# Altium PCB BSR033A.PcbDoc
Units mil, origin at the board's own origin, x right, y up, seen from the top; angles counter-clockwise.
Board outline 1950 x 1400 mil, 2 copper layers (Top Layer, Bottom Layer), stack 61.2 mil thick; 52 components, 17 nets, 86 pads, 24 vias.
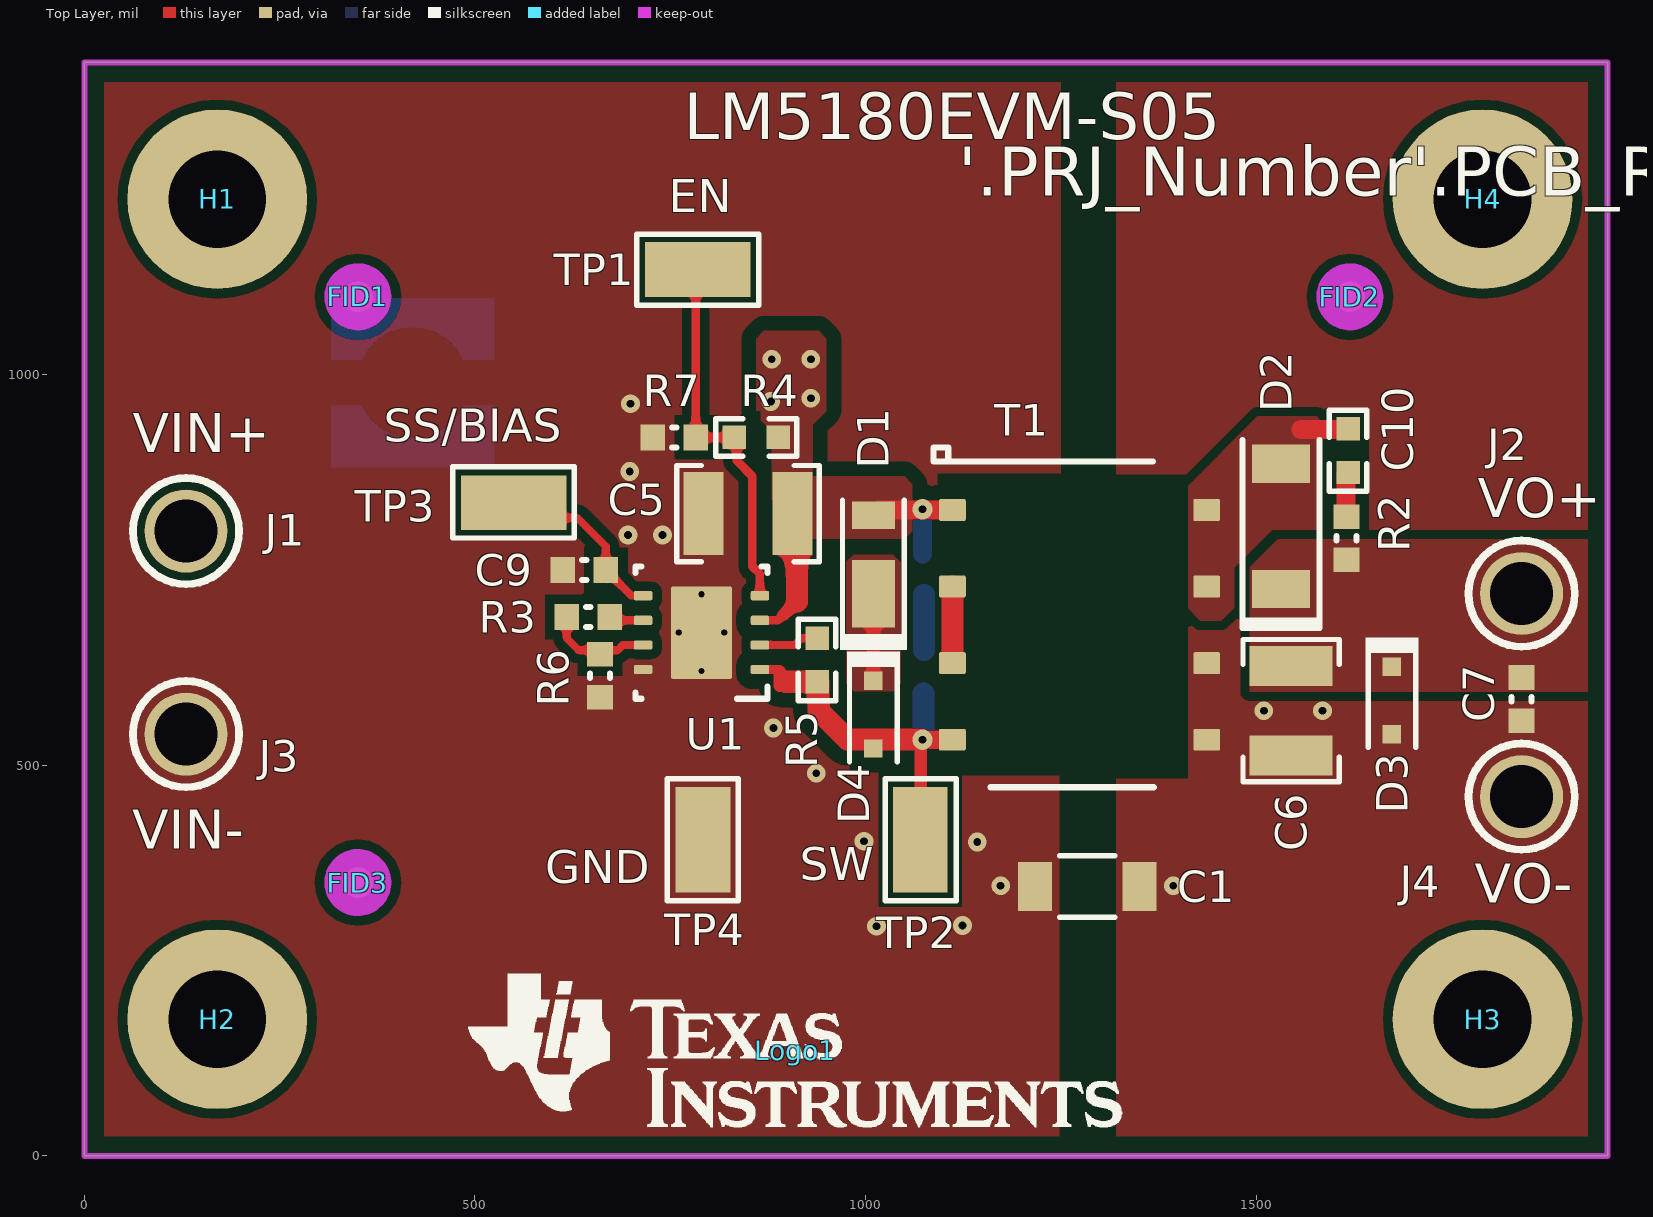
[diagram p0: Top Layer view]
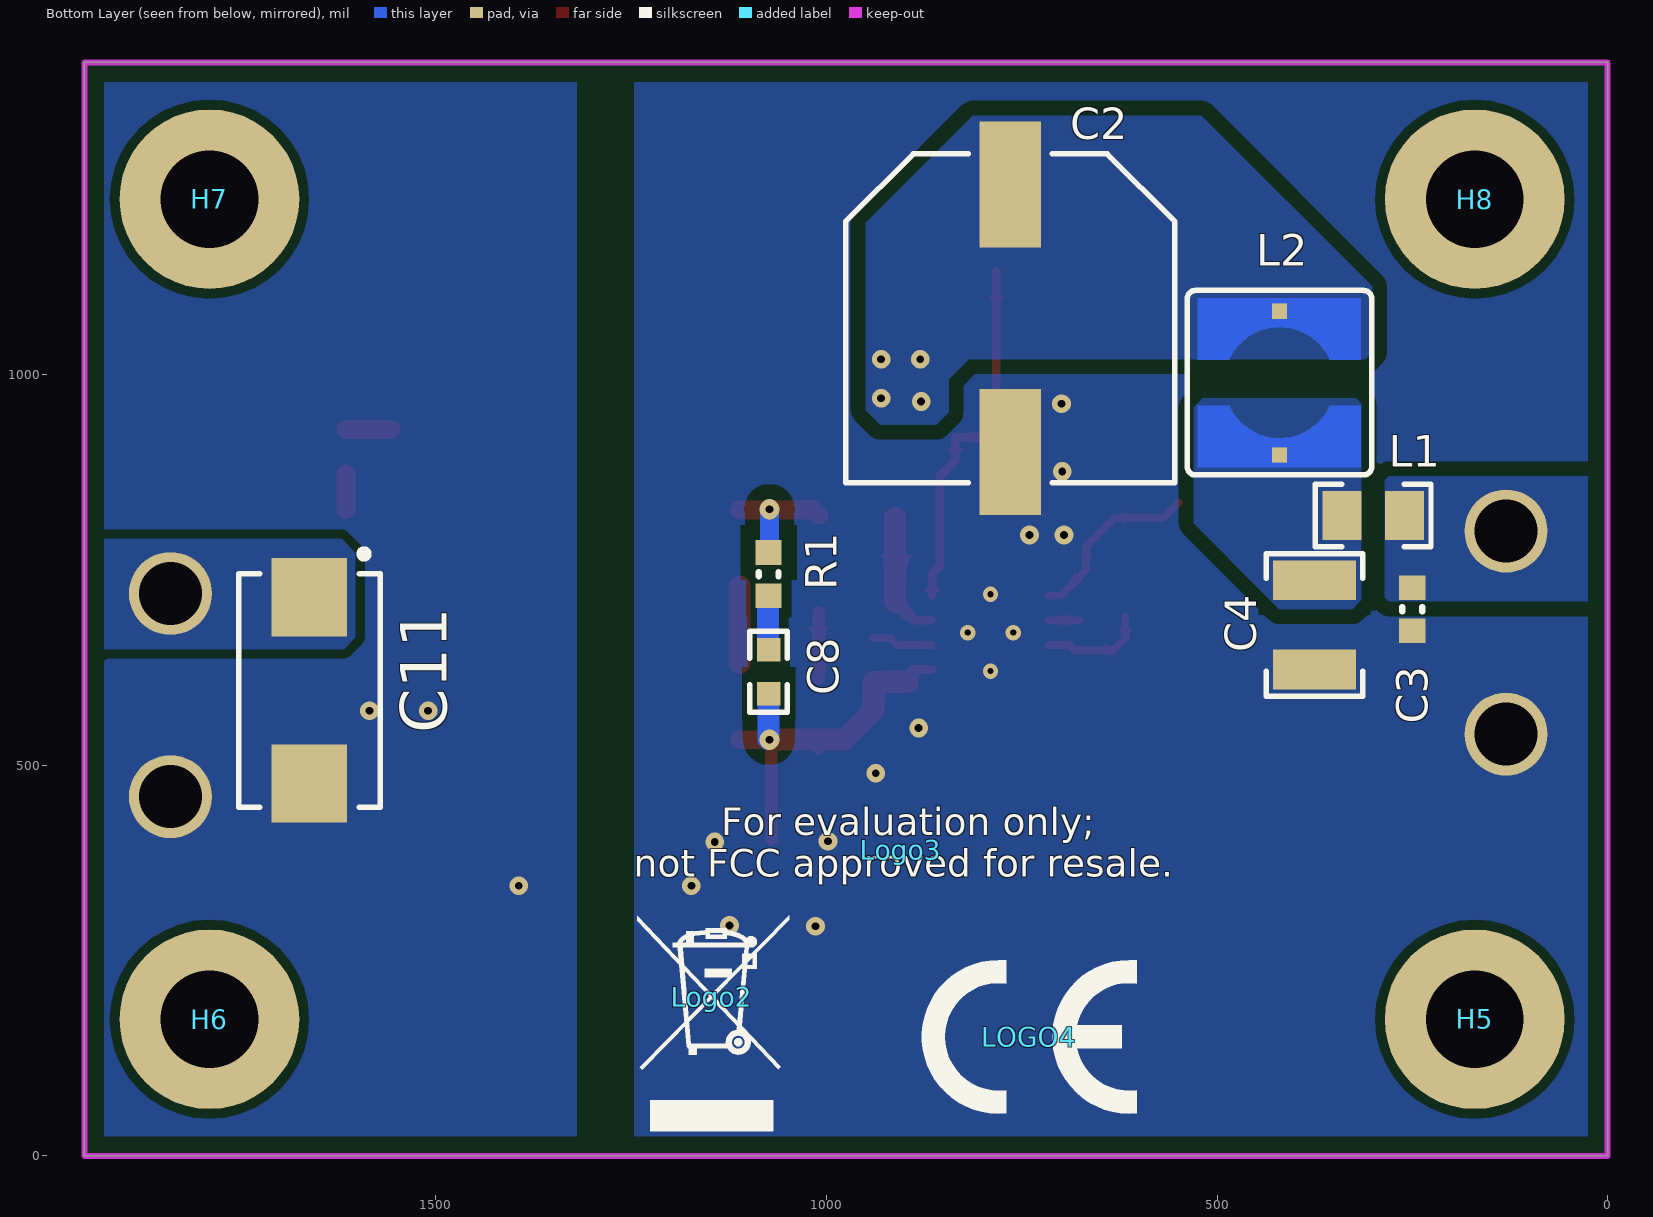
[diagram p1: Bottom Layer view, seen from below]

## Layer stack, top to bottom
Top Solder: solder mask 0.4, Solder Resist, Dk 3.5
Top Layer: signal copper 1.4
Dielectric1: core 58.4, FR-4, Dk 4.8
Bottom Layer: signal copper 1.4
Bottom Solder: solder mask 0.4, Solder Resist, Dk 3.5

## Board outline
0,0 1950,0 1950,1400 0,1400

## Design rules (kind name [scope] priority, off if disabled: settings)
AcuteAngle [All] p1: minimum=4.50000000000000E+0001 checktracksonly=FALSE
AssemblyTestPointUsage [All] p1: valid=2
BoardOutlineClearance BoardOutlineClearance_MountingHoles [OnCopper and InComponentClass('Mounting Holes')] p1: gap=40 ignorepadtopadclearanceinfootprint=FALSE
BoardOutlineClearance BoardOutlineClearance_Poly [OnCopper and IsPoly] p2: gap=25 ignorepadtopadclearanceinfootprint=FALSE
BoardOutlineClearance [OnCopper and Not InComponentClass('Logo') and not InComponentClass('FiducialMark') and not InRegion(1000,500,4000,800) and not InPoly] p3: gap=50 ignorepadtopadclearanceinfootprint=FALSE
Clearance Clearance_HV_Nets [InNetClass('HV_Nets')] p1: gap=19 ignorepadtopadclearanceinfootprint=FALSE
Clearance Clearance_Keepouts [((IsTrack Or IsArc) And Not InPoly) And IsFree and IsKeepOut vs ((IsTrack Or IsArc) And Not InPoly) And IsFree and IsKeepOut] p2: gap=0 ignorepadtopadclearanceinfootprint=FALSE
Clearance Clearance_Poly [InPolygon] p3: gap=12 ignorepadtopadclearanceinfootprint=FALSE
Clearance Clearance_FiducialMark [IsKeepOut and InComponentClass('FiducialMark') vs IsPad and InComponentClass('FiducialMark')] p4: gap=0 ignorepadtopadclearanceinfootprint=FALSE
Clearance [All] p5: gap=7.87 ignorepadtopadclearanceinfootprint=FALSE except(0: Arc-Hole Track-Hole SMDPad-Hole THPad-Hole Via-Hole Fill-Hole Poly-Hole Region-Hole Text-Hole)
ComponentClearance ComponentClearance_MountingHoles_FiducialMarks [InComponentClass('Mounting Holes') vs InComponentClass('FiducialMark')] p1: gap=50 collisioncheckmode=3 verticalgap=10 showdistances=FALSE
ComponentClearance ComponentClearance_Shunt [InComponentClass('Header') vs InComponentClass('Shunt')] p2: gap=0 collisioncheckmode=3 verticalgap=0 showdistances=FALSE
ComponentClearance ComponentClearance_Logo [InComponentClass('Logo')] p3: gap=50 collisioncheckmode=3 verticalgap=10 showdistances=FALSE
ComponentClearance ComponentClearance_ScrewToNut [(HasFootprint('NY PMS 440 0025 PH')) vs (HasFootprint('Keystone_1902C'))] p4: gap=5 collisioncheckmode=3 verticalgap=10 showdistances=FALSE
ComponentClearance ComponentClearance_MountingHoles [InComponentClass('Mounting Holes')] p5: gap=0 collisioncheckmode=3 verticalgap=0 showdistances=FALSE
ComponentClearance ComponentClearance_SmallPassives [HasFootprint('0201*') or HasFootprint('0402*') or HasFootprint('0508') or HasFootprint('0603*') or HasFootprint('0612') or HasFootprint('0805*') or HasFootprint('0815*') or HasFootprint('0830*') or HasFootprint('1206*') or HasFootprint('1210*') or HasFootprint('1808*') or HasFootprint('1812*') or HasFootprint('1825*') or HasFootprint('2010*') or HasFootprint('2220*') or HasFootprint('2225*') or HasFootprint('2512*') or HasFootprint('2728*') or HasFootprint('3518*') vs HasFootprint('0201*') or HasFootprint('0402*') or HasFootprint('0508') or HasFootprint('0603*') or HasFootprint('0612') or HasFootprint('0805*') or HasFootprint('0815*') or HasFootprint('0830*') or HasFootprint('1206*') or HasFootprint('1210*') or HasFootprint('1808*') or HasFootprint('1812*') or HasFootprint('1825*') or HasFootprint('2010*') or HasFootprint('2220*') or HasFootprint('2225*') or HasFootprint('2512*') or HasFootprint('2728*') or HasFootprint('3518*')] p6: gap=14.96 collisioncheckmode=3 verticalgap=10 showdistances=FALSE
ComponentClearance ComponentClearance_THtoSMT [IsThruComponent vs IsSMTComponent] p7: gap=20 collisioncheckmode=3 verticalgap=30 showdistances=FALSE
ComponentClearance ComponentClearance_THtoTH [IsThruComponent vs IsThruComponent] p8: gap=30 collisioncheckmode=3 verticalgap=30 showdistances=FALSE
ComponentClearance [All] p9: gap=10 collisioncheckmode=3 verticalgap=10 showdistances=FALSE
DiffPairsRouting [All] p1: maxlimit=100 minlimit=10 mostfreqgap=10 toplayer_minwidth=15 toplayer_maxwidth=15 toplayer_prefwidth=15 bottomlayer_minwidth=15 bottomlayer_maxwidth=15 bottomlayer_prefwidth=15 maxuncoupledlength=1000
FabricationTestPointUsage TestPointUsage [All] p1: valid=2 allowmultiple=FALSE
FabricationTestpoint Testpoint [All] p1: side=3 testpointundercomponent=TRUE minsize=40 maxsize=100 preferedsize=60 minholesize=0 maxholesize=40 preferedholesize=32 testpointgrid=1 allowsidetop=TRUE allowsidebottom=TRUE usegrid=TRUE gridtolerance=0.01
FanoutControl Fanout_LCC [IsLCC] p1: bgadir=Out bgaviamode=Centered fanoutstyle=Auto fanoutdirection=Alternating viagrid=1 // Fanout_LCC (Default Rule)
FanoutControl Fanout_BGA [IsBGA] p2: bgadir=Out bgaviamode=Centered fanoutstyle=Auto fanoutdirection=Alternating viagrid=1 // Fanout_BGA (Default Rule)
FanoutControl Fanout_Default [All] p4: bgadir=Out bgaviamode=Centered fanoutstyle=Auto fanoutdirection=Alternating viagrid=1 // Fanout_Default (Default Rule)
FanoutControl Fanout_Small [(CompPinCount < 5)] p5: bgadir=Out bgaviamode=Centered fanoutstyle=Auto fanoutdirection=OutThenIn viagrid=1 // Fanout_Small (Default Rule)
HoleSize [All] p1: absolutevalues=TRUE maxlimit=251 minlimit=7.87 maxpercent=80.000 minpercent=20.000
MinimumAnnularRing MinimumAnnularRing_ThermalPadVias [IsVia and InAnyComponent] p1: minimumring=5.91
MinimumAnnularRing [All] p2: minimumring=7
MinimumSolderMaskSliver MinimumSolderMaskSliver_Logo [InComponentClass('Logo') vs InComponentClass('Logo')] p1: minsoldermaskwidth=0.7
MinimumSolderMaskSliver [All] p2: minsoldermaskwidth=3.94
PlaneConnect [All] p1: planeconnectstyle=Relief reliefexpansion=10 reliefentries=4 reliefconductorwidth=10 reliefairgap=10
PolygonConnect [All] p1: connectstyle=Direct reliefconductorwidth=10 reliefentries=4 polygonreliefangle="90 Angle" airgapwidth=10
RoutingVias ThermalPadVias [IsVia and InAnyComponent] p1: holewidth=7.87 width=19.68 viastyle="Through Hole" minholewidth=7.87 minwidth=19.68 maxholewidth=12.99 maxwidth=23.62
RoutingVias [All] p2: holewidth=16 width=34 viastyle="Through Hole" minholewidth=7.87 minwidth=12 maxholewidth=40 maxwidth=65
SilkToBoardRegionClearance [Not ((IsComment or IsDesignator) And (Hide <> 'False')) and not InRegion(1000,500,4000,800)] p1:
SilkToSilkClearance SilkToSilkClearance_Pb-FreeLogo [(HasFootprint('Pb-Free_Overlay_Medium') OR HasFootprint('Pb-Free_Overlay_Small')) vs (HasFootprint('Pb-Free_Overlay_Medium') OR HasFootprint('Pb-Free_Overlay_Small'))] p1: silktosilkclearance=0
SilkToSilkClearance [All] p2: silktosilkclearance=4
SilkToSolderMaskClearance [IsPad] p1: minsilkscreentomaskgap=5 clearancetoexposedcopper=TRUE
SilkToSolderMaskClearance "Silk to Solder Mask Opening" [All] p2: minsilkscreentomaskgap=4 clearancetoexposedcopper=FALSE
SolderMaskExpansion [All] p1: expansion=1.97
Width [All] p1: maxlimit=100 minlimit=6 preferedwidth=10 checkconnectedcopper=TRUE
15 further rules are at their usual default settings.

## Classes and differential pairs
component class "Mounting Holes": H1 H2 H3 H4 H5 H6 H7 H8
net class BSR033A_Nets: GND NetC2_1 NetC3_1 NetC4_2 NetC6_1 NetC8_1 NetC8_2 NetC9_1 NetC10_1 NetC10_2 NetD1_1 NetR3_1 NetR3_2 NetR4_1 NetR5_1 NetT1_2 NetT1_3 SGND
net class HV_Nets: NetC2_1 NetC3_1 NetC4_2 NetC8_2
component class AssemblyNote: ZZ1 ZZ2 ZZ3
component class FiducialMark: FID1 FID2 FID3
component class BSR033A_Hardware: FID1 FID2 FID3 H1 H2 H3 H4 H5 H6 H7 H8 Logo1 Logo2 Logo3 LOGO4 ZZ1 ZZ2 ZZ3
component class Logo: Logo1
component class BSR033A: C1 C2 C3 C4 C5 C6 C7 C8 C9 C10 C11 D1 D2 D3 D4 J1 J2 J3 J4 L1 L2 R1 R2 R3 R4 R5 R6 R7 SS/Bias T1 TP1 TP2 TP3 TP4 U1

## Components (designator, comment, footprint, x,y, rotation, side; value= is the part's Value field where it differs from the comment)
C1 "202R18W102KV4E" 1206_190 1284,345 r180 top value=1000pF
C2 "EEE-FK2A330P" SM_RADIAL_G 764.72,1072.33 r270 bottom value=33uF
C3 "GRM188R72A104KA35J" 0603L 250,700 r270 bottom value=0.1uF
C4 "GRM32DC72A475KE01L" 1210_220 375,680 r90 bottom value=4.7uF
C5 "GRM32DC72A475KE01L" 1210_220 849.5,822.27 r0 top value=4.7uF
C6 "GRM32EC80J107ME20L" 1210_270 1545,570 r270 top value=100uF
C7 "GRM188R72A104KA35J" 0603L 1840,585 r270 top value=0.1uF
C8 "GRM1885C2A220JA01D" 0603_HV 1074,620 r270 bottom value=22pF
C9 "GCM188R71E473KA37D" 0603L 640,750 r180 top value=0.047uF
C10 "GRM1885C2A220JA01D" 0603_HV 1618,903 r90 top value=22pF
C11 "T598D107M010ATE025" 7343-31 1662,596 r270 bottom value=220uF
D1 "DFLZ24-7" PowerDI123 1010,770 r90 top value=24V
D2 "40V" SMAF 1532,806 r90 top
D3 "MMSZ5232BS-7-F" SOD-323 1674,583 r270 top value=5.6V
D4 "75V" SOD-323 1010,565 r270 top
FID1 "Fiducial" Fiducial10-20 350,1100 r270 top
FID2 "Fiducial" Fiducial10-20 1620,1100 r270 top
FID3 "Fiducial" Fiducial10-20 350,350 r270 top
H1 "PMSSS 440 0025 PH" B_F_PMSSS4400025PH 170,1225 r0 top
H2 "PMSSS 440 0025 PH" B_F_PMSSS4400025PH 170,175 r0 top
H3 "PMSSS 440 0025 PH" B_F_PMSSS4400025PH 1790,175 r0 top
H4 "PMSSS 440 0025 PH" B_F_PMSSS4400025PH 1790,1225 r0 top
H5 "1902C" Keystone_1902C 170,175 r180 bottom
H6 "1902C" Keystone_1902C 1790.36,175 r180 bottom
H7 "1902C" Keystone_1902C 1790,1225 r180 bottom
H8 "1902C" Keystone_1902C 170,1225 r180 bottom
J1 "1573-2" Keystone1573-2 130,800 r270 top
J2 "1573-2" Keystone1573-2 1840,720 r0 top
J3 "1573-2" Keystone1573-2 130,540 r0 top
J4 "1573-2" Keystone1573-2 1840,460 r0 top
L1 "742792021" 0805_HV 300,820 r0 bottom value="22 ohm"
L2 "744042100" WE-TPC-M1 420,990 r90 bottom value=10uH
Logo1 "Texas Instruments" TI_Stacked_Overlay_Small 910,135 r0 top
Logo2 "WEEE logo" WEEE_Minimum 1147,204 r180 bottom
Logo3 "FCC disclaimer" FCC_disclaimer_stacked 905,392 r180 bottom
LOGO4 "CE Mark" CE_Mark_5mm 740.25,152.45 r180 bottom
R1 "CRCW0603100RFKEA" 0603L 1074,745 r90 bottom value=100
R2 "CRCW0603100RFKEA" 0603L 1616,791 r90 top value=100
R3 "CRCW0603130KFKEA" 0603L 645,690 r0 top value=130k
R4 "CRCW0603536KFKEA" 0603_HV 860,920 r0 top value=536k
R5 "CRCW0603158KFKEA" 0603_HV 938,635 r270 top value=158k
R6 "CRCW060312K1FKEA" 0603L 660,615 r90 top value=12.1k
R7 "CRCW0603100KFKEA" 0603L 755,920 r0 top value=100k
T1 "YA8779-BL" Coilcraft_YA8779-CL 1274,680 r0 top value=30uH
TP1 "EN" Testpoint_Keystone_Miniature 785,1135 r0 top
TP2 "SW" Testpoint_Keystone_Miniature 1070,405 r90 top
TP3 "SS/BIAS" Testpoint_Keystone_Miniature 549.37,836.18 r180 top
TP4 "GND" Testpoint_Keystone_Miniature 792,405 r270 top
U1 "LM5180QNGURQ1" NGU0008C 790,670 r180 top
ZZ1 "These assemblies must be clean and free from flux and all contaminants.  Use of no clean flux is not acceptable." AssemblyNote 95,3740.56 r0 top
ZZ2 "These assemblies must comply with workmanship standards IPC-A-610 Class 2., unless otherwise specified." AssemblyNote 95,3652 r0 top
ZZ3 "Mounting hardware H1 thru H8 to be installed in corner holes provided.  Screw inserted from component side, standoff on solder side." AssemblyNote 94,3552 r0 top

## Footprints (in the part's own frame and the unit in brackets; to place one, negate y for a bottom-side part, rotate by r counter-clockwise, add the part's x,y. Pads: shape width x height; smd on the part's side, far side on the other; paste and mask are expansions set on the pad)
0603_HV [mil] "Ernesto recommended land pattern.  26 mil between pads."
  rect 30x30 smd: 1(-28,0) 2(28,0)
  silkscreen extent -52,-24 52,24, body extent -34,-19 34,19, height 39
0603L [mm] "0603 from SM-752 data"
  rect 0.8x0.85 smd: 1(-0.7,0) 2(0.7,0)
  silkscreen extent -0.07,-0.33 0.07,0.33, body extent -0.87,-0.47 0.87,0.47, height 1
0805_HV [mil] "0805 with 30mil clearance between pads"
  rect 50x63 smd: 1(-40,0) 2(40,0)
  silkscreen extent -74,-40 74,40, body extent -43,-29 43,29, height 57
1206_190 [mm] "1206_190"
  rect 1.1x1.6 smd: 1(-1.7,0) 2(1.7,0)
  silkscreen extent -0.9,-1 0.9,1, body extent -1.75,-0.95 1.75,0.95, height 1.9
1210_220 [mm] "1210"
  rect 1.3x2.7 smd: 1(-1.45,0) 2(1.45,0)
  silkscreen extent -2.32,-1.57 2.32,1.57, body extent -1.7,-1.35 1.7,1.35, height 2.2
1210_270 [mm] "1210"
  rect 1.3x2.7 smd: 1(-1.45,0) 2(1.45,0)
  silkscreen extent -2.32,-1.57 2.32,1.57, body extent -1.7,-1.35 1.7,1.35, height 2.7
7343-31 [mm] "Medium Density based on Kemet T495 dimensions"
  rect 2.55x2.45 smd: 1(-3.025,0) 2(3.025,0)
  silkscreen extent -4.56,-2.3 3.8,2.3, body extent -3.8,-2.3 3.8,2.3, height 3.1
AssemblyNote [mil] "Assembly Note"
B_F_PMSSS4400025PH [mil] "MACHINE SCREW PAN PHILLIPS 4-40"
  round 230 hole 125: 1(0,0)
  body extent -109,-109 110,110, height 79
CE_Mark_5mm [mil] "Minimum text height for CE Mark"
  silkscreen extent -138,-98 138,98
Coilcraft_YA8779-CL [mm] "SMD, 8-Leads, Body 9.3x10.2mm, Pitch 2.49mm"
  rrect14% 0.87x0.71 smd: 1(-4.135,3.735) 2(-4.135,1.245) 3(-4.135,-1.245) 4(-4.135,-3.735) 5(4.135,-3.735) 6(4.135,-1.245) 7(4.135,1.245) 8(4.135,3.735)
  body extent -4.65,-5.1 4.65,5.1, height 10.6
FCC_disclaimer_stacked [mil]
Fiducial10-20 [mm]
  round 1 smd mask+0.5: 1(0,0)
  Top Layer keep-out circle w1.178: c0,0 r0.5
Keystone1573-2 [mm] "Double Turret"
  round 2.7 hole 2.05: 1(0,0)
  silkscreen extent -1.73,-1.73 1.73,1.73, body extent -1.18,-1.18 1.17,1.18, height 4.72
Keystone_1902C [mil] "Hex Standoff, 4-40 threaded, nylon"
  round 1 on Mech4: 0(0,0)
  body extent -145,-126 146,126, height 501
NGU0008C [mm] "SON, 8-Leads, Body 4x4mm, Pitch 0.8mm"
  rrect33% 0.6x0.3 smd: 1(-1.9,1.2) 2(-1.9,0.4) 3(-1.9,-0.4) 4(-1.9,-1.2) 5(1.9,-1.2) 6(1.9,-0.4) 7(1.9,0.4) 8(1.9,1.2)
  rrect8% 1.75x1.31 on Top Paste: 9(0,0.755) 9(0,-0.755)
  rrect5% 1.98x3 smd paste-1.5: 9(0,0)
  silkscreen extent -2.15,-2.15 2.15,2.15, body extent -2,-2 2,2, height 0.77
PowerDI123 [mm] "Diodes Inc recommended land pattern, document number DS30628 Rev. 6-2"
  rect 2.2x1.4 smd: 1(-1.275,0)
  rect 0.9x1.4 smd: 2(1.275,0)
  silkscreen extent -3.1,-1.09 1.76,1.09, body extent -2.38,-0.97 1.52,0.96, height 1
SM_RADIAL_G [mm] "10 x 10.2mm:  Panasonic G"
  rect 4.1x2 smd: 1(-4.35,0) 2(4.35,0)
  silkscreen extent -5.35,-5.35 5.35,5.35, body extent -5.25,-5.25 5.25,5.25, height 10.5
SMAF [mm] "SMD, 2-Leads, Body 3.8x2.5mm"
  rect 1.24x1.89 smd: 1(-2.04,0) 2(2.04,0)
  silkscreen extent -3.4,-1.3 2.8,1.3, body extent -2.35,-1.25 2.35,1.25, height 1
SOD-323 [mm] "NXP recommended land pattern"
  rect 0.6x0.6 smd paste-0.05: 1(-1.1,0) 2(1.1,0)
  silkscreen extent -2.06,-0.86 1.53,0.86, body extent -1.3,-0.67 1.3,0.68, height 1.1
Testpoint_Keystone_Miniature [mil] "Miniature SMT test point"
  rect 135x70 smd: 1(0,0)
  silkscreen extent -78,-46 78,45, body extent -52,-20 52,20, height 61
TI_Stacked_Overlay_Small [mil]
  silkscreen extent -418,-98 418,98
WE-TPC-M1 [mm] "Wurth Elektronik recommended land pattern"
  rect 0.5x0.5 smd: 1(-2.35,0) 2(2.325,0)
  Top Layer region: -0.75,1.64 -1.005,1.504 -1.279,1.279 -1.504,1.005 -1.671,0.692 -1.774,0.353 -1.809,0 -1.774,-0.353 -1.671,-0.692 -1.504,-1.005 -1.279,-1.279 -1.005,-1.504 -0.75,-1.64 -0.75,-2.65 -2.75,-2.65 -2.75,2.65 -0.75,2.65
  Top Layer region: 0.75,1.64 1.005,1.504 1.279,1.279 1.504,1.005 1.671,0.692 1.774,0.353 1.809,0 1.774,-0.353 1.671,-0.692 1.504,-1.005 1.279,-1.279 1.005,-1.504 0.75,-1.64 0.75,-2.65 2.75,-2.65 2.75,2.65 0.75,2.65
  silkscreen extent -3,-3 3,3, body extent -2.5,-2.5 2.5,2.5, height 2
WEEE_Minimum [mil] "WEEElie bin"
  silkscreen extent -95,-172 99,104

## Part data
C1: library part CMP-0008572-2, "CAP, CERM, 1000 pF, 2000 V, +/- 10%, X7R, 1206_190", Cap_Case=1206, Manufacturer="Johanson Technology", TempCo=X7R, Tolerance_%=10%, Value1=Unknown, Value2=2000V, ValueDisplayed=1000pF
C2: library part CMP-0011203-2, "CAP, AL, 33 uF, 100 V, +/- 20%, 0.7 ohm, AEC-Q200 Grade 2, SMD", Cap_Case=G, Manufacturer=Panasonic, Supplier Part Number 1=PCE3846CT-ND, Tolerance_%=20%, Value1="0.7 ohm", Value2=100V, ValueDisplayed=33uF
C3 C7: library part CMP-0007470-5, "CAP, CERM, 0.1 uF, 100 V, +/- 10%, X7R, 0603", Cap_Case=0603, Manufacturer=MuRata, Supplier Part Number 1=490-6439-1-ND, TempCo=X7R, Tolerance_%=10%, Value1=Unknown, Value2=100V, ValueDisplayed=0.1uF
C4 C5: library part CMP-0009182-2, "CAP, CERM, 4.7 uF, 100 V, +/- 10%, X7S, 1210", Cap_Case=1210, Manufacturer=MuRata, Supplier Part Number 1=81-GRM32DC72A475KE1L, TempCo=X7S, Tolerance_%=10%, Value1=Unknown, Value2=100V, ValueDisplayed=4.7uF
C6: library part CMP-0009199-2, "CAP, CERM, 100 uF, 6.3 V, +/- 20%, X6S, 1210", Cap_Case=1210, Manufacturer=MuRata, Supplier Part Number 1=GRM32EC80J107ME20L-ND, TempCo=X6S, Tolerance_%=20%, Value1=Unknown, Value2=6.3V, ValueDisplayed=100uF
C8 C10: library part CMP-0007255-4, "CAP, CERM, 22 pF, 100 V, +/- 5%, C0G/NP0, 0603", Cap_Case=0603, Manufacturer=MuRata, Supplier Part Number 1=490-1335-1-ND, TempCo=C0G/NP0, Tolerance_%=5%, Value1=Unknown, Value2=100V, ValueDisplayed=22pF
C9: library part CMP-0007141-5, "CAP, CERM, 0.047 uF, 25 V, +/- 10%, X7R, AEC-Q200 Grade 1, 0603", Cap_Case=0603, Manufacturer=MuRata, Supplier Part Number 1=490-8018-1-ND, TempCo=X7R, Tolerance_%=10%, Value1=Unknown, Value2=25V, ValueDisplayed=0.047uF
C11: library part CMP-0074683-2, "CAP, Aluminum Polymer, 220 µF, 6.3 V,+/- 20%, 0.01 ohm, 7343-31 SMD", Cap_Case=7343-31, Manufacturer=MuRata, PartNumber=ECASD60J227M010K00, Supplier Part Number 1=490-12529-1-ND, Tolerance_%=20%, Value1="0.01 ohm", Value2=6.3V, ValueDisplayed=220µF
D1: library part CMP-0005415-2, "Diode, Zener, 24 V, 1 W, PowerDI123", Manufacturer="Diodes Inc.", Power_W=1W, Supplier Part Number 1=DFLZ24DICT-ND
D2: library part CMP-0028855-1, "Diode, Schottky, 40 V, 3 A, AEC-Q101, SMAF", Manufacturer="Fairchild Semiconductor", PartNumber=FSV340AF, Supplier Part Number 1=FSV340AFCT-ND, Value1=3A, Value2=0.5V
D3: library part CMP-0005855-1, "Diode, Zener, 5.6 V, 200 mW, SOD-323", Manufacturer="Diodes Inc.", Power_W=200mW, Supplier Part Number 1=MMSZ5232BS-FDICT-ND, Value1=0.2W
D4: library part CMP-0029019-1, "Diode, Ultrafast, 75 V, 0.25 A, SOD-323", Manufacturer="Central Semiconductor", PartNumber=CMDD4448, Value1=0.25A, Value2=1.2V
FID1 FID2 FID3: "Fiducial mark.  There is nothing to buy or mount.", Manufacturer=N/A
H1 H2 H3 H4: library part CMP-0003715-1, "MACHINE SCREW PAN PHILLIPS 4-40", Manufacturer="B&F Fastener Supply", Supplier Part Number 1=H703-ND
H5 H6 H7 H8: library part CMP-0003610-1, "Standoff, Hex, 0.5\"L #4-40 Nylon", Manufacturer=Keystone, Supplier Part Number 1=36-1902C-ND
J1 J2 J3 J4: library part CMP-0055119-1, "Terminal, Turret, TH, Double", Manufacturer=Keystone, Supplier Part Number 1=36-1573-2-ND
L1: library part CMP-0003072-1, "Ferrite Bead, 22 ohm @ 100 MHz, 6 A, 0805", Manufacturer="Wurth Elektronik", Supplier Part Number 1=732-4637-1-ND, Value1="0.008 ohm", Value2=6A, ValueDisplayed="22 ohm"
L2: library part CMP-0063804-1, "Inductor, Shielded Drum Core, Ferrite, 10 uH, 1 A, 0.12 ohm, SMD", Manufacturer="Wurth Elektronik", Supplier Part Number 1=732-1025-1-ND, Value1="0.12 ohm", Value2=1A, ValueDisplayed=10uH
Logo1: library part TI_Logo, "Texas Instrument Corporate Signature"
Logo2: library part CMP-0074769-1
Logo3: library part FCC_disclaimer, "FCC_disclaimer"
R1 R2: library part CMP-0021991-3, "RES, 100, 1%, 0.1 W, 0603", Manufacturer=Vishay-Dale, Power_W=100mW, Supplier Part Number 1=541-100HCT-ND, TempCo="100 ppm/C", Tolerance_%=1%, Value2=0.1W, Value_Code=100R, ValueDisplayed=100
R3: library part CMP-0022036-4, "RES, 130 k, 1%, 0.1 W, AEC-Q200 Grade 0, 0603", Manufacturer=Vishay-Dale, Power_W=100mW, Supplier Part Number 1=541-130KHCT-ND, TempCo="100 ppm/C", Tolerance_%=1%, Value2=0.1W, Value_Code=130k
R4: library part CMP-0022488-4, "RES, 536 k, 1%, 0.1 W, AEC-Q200 Grade 0, 0603", Manufacturer=Vishay-Dale, Power_W=100mW, Supplier Part Number 1=541-536KHCT-ND, TempCo="100 ppm/C", Tolerance_%=1%, Value2=0.1W, Value_Code=536k
R5: library part CMP-0022064-4, "RES, 158 k, 1%, 0.1 W, AEC-Q200 Grade 0, 0603", Manufacturer=Vishay-Dale, Power_W=100mW, Supplier Part Number 1=541-158KHCT-ND, TempCo="100 ppm/C", Tolerance_%=1%, Value2=0.1W, Value_Code=158k
R6: library part CMP-0022030-3, "RES, 12.1 k, 1%, 0.1 W, 0603", Manufacturer=Vishay-Dale, Power_W=100mW, Supplier Part Number 1=541-12.1KHCT-ND, TempCo="100 ppm/C", Tolerance_%=1%, Value2=0.1W, Value_Code=12k1, ValueDisplayed=12.1k
R7: library part CMP-0021990-4, "RES, 100 k, 1%, 0.1 W, AEC-Q200 Grade 0, 0603", Manufacturer=Vishay-Dale, Power_W=100mW, Supplier Part Number 1=541-100KHCT-ND, TempCo="100 ppm/C", Tolerance_%=1%, Value2=0.1W, Value_Code=100k
T1: library part CMP-0085524-1, "Transformer, 30 uH, SMD", Manufacturer=Coilcraft, ValueDisplayed=30µH
TP1 TP2 TP3 TP4: library part CMP-0055152-1, "Test Point, Miniature, SMT", Manufacturer=Keystone, PartNumber=5015, Supplier Part Number 1=36-5015TR-ND
U1: library part CMP-0078633-2, "70-V PSR Flyback Converter With 100-V, 1.2-A Power Switch and Ultra-Low IQ, NGU0008C (WSON-8)", Alternate Manufacturer="Texas Instruments", Alternate PartNumber=LM5180QNGUTQ1
ZZ1 ZZ2 ZZ3: library part AssemblyNote

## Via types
v1: diameter 24, hole 10, Top Layer to Bottom Layer, tented both sides, 18 vias
v2: diameter 19.68, hole 7.87, Top Layer to Bottom Layer, 4 vias
v3: diameter 26, hole 10, Top Layer to Bottom Layer, 2 vias

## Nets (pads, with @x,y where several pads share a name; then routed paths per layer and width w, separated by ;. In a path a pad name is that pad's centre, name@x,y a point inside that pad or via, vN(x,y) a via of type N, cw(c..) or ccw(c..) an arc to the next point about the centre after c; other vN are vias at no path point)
GND: C1.2 C2.2 C3.2 C4.1 C5.1 C9.2 J3.1 R6.1 R7.1 TP4.1 U1.8 U1.9@790,670
  other v1: 1014,294 1124,295 1173,346 1143,402 998,403 937,490 882,548 696,795 740,795 698.14,876.2 699,963
  other v2: 790,620.79 760.86,670 819.13,670 790,719.21
NetC2_1: C2.1 C5.2 D1.2 L2.2 R1.2 R4.2 T1.1 U1.3 | length 321.6
  Top Layer w11: U1.3 887.88,685.75 894.25,692.12
  Top Layer w15: 894.25,692.12 912.13,710
  Top Layer w24: D1.2 1016.85,827.05 T1.1
  Top Layer w28: 912.13,710 C5.2@912.13,816.73
  Bottom Layer w24: R1.2@1073,770.56 v3@1073,824
  other v1: 878.8,965.86 930,970 880,1020 930,1020
  other v3: 1073,828
NetC3_1: C3.1 J1.1 L1.1
NetC4_2: C4.2 L1.2 L2.1
NetC6_1: C6.1 C7.1 C11.1 D2.1 D3.1 J2.1 R2.1
NetC8_1: C8.1 R1.1 | length 70.4
  Bottom Layer w28: C8.1@1075,648 R1.1@1075,718.44
NetC8_2: C8.2 D4.2 R5.2 T1.4 TP2.1 U1.1 | length 493.9
  Top Layer w11: U1.1 890,622.75
  Top Layer w16: 890,602 890,620 ; 890,615 898,607 ; D4.2 D4.2@1011,522.69 ; TP2.1 1070,425 1071,426 v3@1071,532.95
  Top Layer w24: v3@1084,532.95 T1.4
  Top Layer w28: 898,607 940,607 940,570 977,533 D4.2@1010,533 ; D4.2@1011,533 1037.91,533 1037.95,532.95 v3@1071,532.95
  Bottom Layer w28: v3@1074,533.95 C8.2
  other v3: 1073,532.95
NetC9_1: C9.1 TP3.1 U1.5 | length 232.9
  Top Layer w10: TP3.1 568.56,817 631,817 667.56,780.44 C9.1 700.32,717.24 U1.5
NetC10_1: C10.1 R2.2 | length 45.4
  Top Layer w24: R2.2@1615,827.58 C10.1@1615,873.02
NetC10_2: C10.2 D2.2 T1.7 T1.8 | length 57.6
  Top Layer w24: 1557.44,930.05 C10.2@1615,930.05
NetD1_1: D1.1 D4.1 | length 84
  Top Layer w16: D4.1@1010,611.54 D1.1@1010,695.53
NetR3_1: R3.1 R6.2 U1.7 | length 134.2
  Top Layer w10: R3.1@617.56,690 R3.1 617.44,662.76 632.64,647.56 660,647.56 682.56,647.56 689.25,654.25 U1.7
NetR3_2: R3.2 U1.6 | length 38.4
  Top Layer w10: R3.2@676.81,685.75 U1.6
NetR4_1: R4.1 R7.2 TP1.1 U1.4 | length 479.6
  Top Layer w11: R7.2 TP1.1@782.56,1132.56 ; R7.2@783.05,920 797.56,920 835,920 835,890.27 855,870.27 855,755 864.8,745.2 U1.4
NetR5_1: R5.1 U1.2 | length 77.8
  Top Layer w10: U1.2 909.25,654.25 ; 910,655 918,663 R5.1@940,663
NetT1_2: T1.2 T1.3 | length 98
  Top Layer w28: T1.3 T1.2
SGND: C1.1 C6.2 C7.2 C11.2 D3.2 J4.1 T1.5 T1.6
  other v1: 1394,346 1510,570 1585,570
pads on no net: FID1.1 FID2.1 FID3.1 H1.1 H2.1 H3.1 H4.1 H5.0 H6.0 H7.0 H8.0 U1.9@790,640.27 U1.9@790,699.72

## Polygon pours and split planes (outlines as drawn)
NetD1_1 on Top Layer "Top Layer-No Net 5" (solid, pour order 122): 985,770 1035,770 1045,760 1045,604.5 1035.5,595 985,595 975.47,604.53 975.47,760.47
NetC2_1 on Top Layer "Top Layer-No Net 4" (solid, pour order 121): 860,948 860,1046.26 870,1056.26 940,1056.26 950,1046.26 950,953.74 929.26,933 875,933
NetC2_1 on Top Layer "Bottom Layer-No Net 3" (solid, pour order 123): 1050,790 889,790 889,870 1050,870 1060,860 1060,800
NetC6_1 on Top Layer "Top Layer-No Net 2" (solid, pour order 125): 1945.8,594.61 1491.87,594.61 1491.87,753.87 1527.61,789.61 1945.8,789.61
GND on Top Layer "Top Layer-No Net" (solid, pour order 127): 0,1400 1060,1400 1250,1400 1250,874 1092,874 1092,487 1247.76,487 1247.76,0 0,0
SGND on Top Layer "Top Layer-No Net 1" (solid, pour order 126): 1400,1400 1321,1400 1321,873 1413,873 1413,483.15 1321,483.15 1321,0 1950,0 1950,1400
NetC10_2 on Top Layer "Top Layer-No Net 3" (solid, pour order 124): 1413,701 1413,857.95 1501.76,946.88 1581.2,947.03 1581.2,802 1521,802 1472,753 1472,702 1455.29,685.29 1428.71,685.29
NetC2_1 on Top Layer "TOP_LAYER_NETC2_1_P120" (solid, pour order 120): 932.52,944 932.52,840 880,840 880,944
NetC2_1 on Bottom Layer "Bottom Layer-No Net 2" (solid, pour order 131): 310,1020 818,1020 843.56,994.44 843.56,952.06 859.18,936.44 931.44,936.44 950,955 950,1195 813,1332 520,1332 301.37,1113.37 301.37,1028.63
NetC4_2 on Bottom Layer "Bottom Layer-No Net 1" (solid, pour order 130): 315,963.27 315,711.85 326.85,700 420,700 440,720 530,810 530,958.27 518.27,970 321.73,970
NetC3_1 on Bottom Layer "Bottom Layer-No Net" (solid, pour order 128): 1,710 280,710 285,715 285,785 285,865 280,870 0,870
SGND on Bottom Layer "Top Layer-No Net 1" (solid, pour order 132): 1320,1400 1320,0 1950,0 1950,1400
GND on Bottom Layer "Top Layer-No Net" (solid, pour order 133): 0,1400 1246,1400 1246,0 0,0
NetC6_1 on Bottom Layer "BOTTOM_LAYER_NETC6_1_P129" (solid, pour order 129): 1950.03,649.06 1618.04,648.96 1603,664 1603,772.13 1620.87,790 1949.06,790

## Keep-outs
Keep-Out Layer:
  the board outline again, w8
  text ".Layer_Name" at 487,-858.49 h60

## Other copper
Top Layer:
  pour cut-out: 1055,777 1090,777 1090,568 1055,568
  text ".Layer_Name" at 487,-858.49 h60
Bottom Layer:
  pour cut-out: 310.05,699.5 288.65,699.5 288.65,881.3 311.79,881.3
  pour cut-out: 301.16,1010 301.16,980 538.84,980 538.84,1010
  text ".Layer_Name" at 487,-858.49 h60

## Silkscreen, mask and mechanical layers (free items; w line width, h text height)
Top Overlay:
  lines w8: 1106,889 1106,907 1087,907 1087,889 1368,889 ; 1160,472 1369,472
  text "LM5180EVM-S05" at 767,1302 h60
  text "'.PRJ_Number'.PCB_Rev" at 1119,1208 h108.27
  text "EN" at 748,1194 h72.83
  text "VIN+" at 62,901 h50
  text "SS/BIAS" at 383,900 h72.83
  text "VO+" at 1784,818 h50
  text "VIN-" at 61,393 h50
  text "SW" at 916,339 h72.83
  text "GND" at 590,335 h72.83
  text "VO-" at 1780,324 h50
  text ".Layer_Name" at 487,-858.49 h60
Bottom Overlay:
  text ".Layer_Name" at 487,-858.49 h60
Top Paste:
  text ".Layer_Name" at 487,-858.49 h60
Bottom Paste:
  text ".Layer_Name" at 487,-858.49 h60
Top Solder:
  text ".Layer_Name" at 487,-858.49 h60
  text ".Layer_Name" at 487,-858.49 h60
Bottom Solder:
  text ".Layer_Name" at 487,-858.49 h60
Drill Guide:
  text ".Layer_Name" at 487,-858.49 h60
M1 Board Outline:
  the board outline again, w10
  text ".Layer_Name" at 487,-858.49 h60
M2 Board Dimensions:
  rectangle: 35,-400 410,-275
  rectangle: -90,-275 35,-150
  lines w7: -90,-275 910,-275 ; 35,-400 35,-150 ; 160,-400 160,-150 ; 410,-400 410,-150 ; 660,-400 660,-150 ; -90,-400 -90,-150 910,-150 910,-400 -90,-400
  text ".Layer_Name" at 487,-858.49 h60
M3 3D STEP Top:
  text ".Layer_Name" at 487,-858.49 h60
M4 3D STEP Bottom:
  text ".Layer_Name" at 487,-858.49 h60
M5 Assembly Top:
  lines w10: -382,-930.17 6218,-930.17 ; -382,-726.83 6220,-726.83 ; -382,-523.5 -382,-1133.5 3623,-1133.5 6220,-1133.5 6220,-523.5 -381.5,-523.5 -381.5,-1133.5 1194,-1133.5 ; 2083,-1133.5 2083,-523.5 ; 3350,-726.83 3350,-523.5 ; 4190,-726.83 4190,-523.5 ; 4812,-1140 4812,-937.17
  text "COMPONENTS MARKED 'DNP' SHOULD NOT BE POPULATED." at 1063.5,-318.5 h60
  text "ASSEMBLY VARIANT:" at 1063,-434 h60
  text ".VariantName" at 2099,-434 h60
  text "PCB VIEWED FROM TOP SIDE" at -318.5,-655.67 h60
  text "BOARD #:" at 2158,-655.67 h60
  text ".PRJ_Number" at 2703.5,-655.67 h60
  text "REV:" at 3548,-655.67 h60
  text ".PCB_Rev" at 3839.5,-655.67 h60
  text "SVN REV:" at 4386,-655.67 h60
  text ".VersionControl_RevNumber" at 4892,-655.67 h60
  text "TID #:" at 2158,-859 h60
  text ".TID" at 2703.5,-859 h60
  text "PLOT NAME =" at -318.5,-1064.34 h60
  text ".plot_File_Name" at 487,-1064.34 h60
  text "GENERATED    :" at 2160,-1064.34 h60
  text ".Print_Date" at 3029.5,-1064.34 h60
  text ".Print_Time" at 3758.5,-1064.34 h60
  text "TEXAS INSTRUMENTS" at 5023,-1064.34 h60
M6 Assembly Bottom:
  lines w10: -382.5,-727.33 6219.5,-727.33 ; -380.5,-930.67 6219.5,-930.67 ; 1025.5,-1140.5 1025.5,-937.67 ; 1647.5,-727.33 1647.5,-524 ; 2487.5,-727.33 2487.5,-524 ; 3754.5,-1134 3754.5,-524 ; 4643.5,-1134 6219,-1134 6219,-524 -382.5,-524 -382.5,-1134 2214.5,-1134 6219.5,-1134 6219.5,-524
  text "COMPONENTS MARKED 'DNP' SHOULD NOT BE POPULATED." at 6012,-318 h60
  text ".VariantName" at 4968,-434 h60
  text "ASSEMBLY VARIANT:" at 6007,-434 h60
  text ".VersionControl_RevNumber" at 945.5,-656.17 h60
  text "SVN REV:" at 1451.5,-656.17 h60
  text ".PCB_Rev" at 1998,-656.17 h60
  text "REV:" at 2289.5,-656.17 h60
  text ".PRJ_Number" at 3134,-656.17 h60
  text "BOARD #:" at 3679.5,-656.17 h60
  text "PCB VIEWED FROM BOTTOM SIDE" at 6156,-656.17 h60
  text ".TID" at 3134,-859.5 h60
  text "TID #:" at 3679.5,-859.5 h60
  text "TEXAS INSTRUMENTS" at 814.5,-1064.84 h60
  text ".Print_Time" at 2079,-1064.84 h60
  text ".Print_Date" at 2808,-1064.84 h60
  text "GENERATED    :" at 3677.5,-1064.84 h60
  text ".plot_File_Name" at 5350.5,-1064.84 h60
  text "PLOT NAME =" at 6156,-1064.84 h60
M9 Title Sheet:
  drawing of 57 lines, arcs and shapes, not listed
  text "1" at 649.84,8036.5 h70
  text "2" at 3145.5,8036.5 h70
  text "3" at 5634.84,8036.5 h70
  text "4" at 8141.51,8036.5 h70
  text "5" at 10640.5,8036.5 h70
  text "6" at 13145.5,8036.5 h70
  text "A" at -506.5,6893.5 h70
  text "A" at 14293.5,6893.5 h70
  text "B" at -506.5,4513.5 h70
  text "B" at 14293.5,4513.5 h70
  text "C" at -506.5,2138.5 h70
  text "C" at 14293.5,2138.5 h70
  text "PROJECT TITLE:" at 11253.5,277.5 h45
  text ".PRJ_Title" at 11303.5,144.17 h70
  text "DESIGNED FOR:" at 11253.5,-23.5 h45
  text ".PRJ_Customer" at 11303.5,-163.5 h70
  text "D" at -506.5,-231.5 h70
  text "D" at 14293.5,-231.5 h70
  text "FILE NAME:" at 11253.5,-323.5 h45
  text ".PCB_File_Name_No_Path" at 11303.5,-443.5 h70
  text "Texas Instruments (TI) and/or its licensors do not warrant the accuracy or completeness of this specification" at 6284,-605.34 h45
  text "ENGINEER:" at 11253.5,-613.5 h45
  text "LAYOUT BY:" at 12758.5,-613.5 h45
  text "or any information contained therein. TI and/or its licensors do not warrant that this design will meet" at 6239.01,-718 h45
  text ".PRJ_Engineer" at 11303.5,-768.49 h70
  text ".PCB_Layout" at 12809,-768.49 h70
  text "the specifications, will be suitable for your application or fit for any particular purpose, or will operate in" at 6239.01,-830.67 h45
  text ".Layer_Name" at 487,-858.49 h60
  text "ALTIUM DESIGNER VERSION:" at 12758.5,-923.5 h45
  text "an implementation. TI and/or its licensors do not warrant that the design is production worthy. You should" at 6239.01,-943.33 h45
  text "completely validate and test your design implementation to confirm the system functionality for your application." at 6284,-1056 h45
  text ".print_Scale" at 11303.5,-1056.83 h70
  text ".Application_BuildNumber" at 12809,-1056.83 h70
  text "1" at 649.84,-1263.5 h70
  text "2" at 3145.5,-1263.5 h70
  text "3" at 5634.84,-1263.5 h70
  text "4" at 8141.51,-1263.5 h70
  text "5" at 10640.5,-1263.5 h70
  text "6" at 13145.5,-1263.5 h70
M10 Fab Notes:
  drawing of 189 lines, arcs and shapes, not listed
  text "DESIGN INFORMATION" at 12292.02,6356.17 h60
  text "MIN. TRACK WIDTH:" at 11647.46,6224.05 h60
  text "8" at 12743.7,6224.05 h60
  text "MIL" at 12898.46,6224.05 h60
  text "MIN. CLEARANCE:" at 11647.46,6099.92 h60
  text "0.2" at 12683.7,6099.93 h60
  text "mm" at 12898.46,6099.92 h60
  text "MIN. VIA PAD SIZE:" at 11647.46,5975.8 h60
  text "24" at 12713.71,5975.8 h60
  text "MIL" at 12898.46,5975.8 h60
  text "0.05mm (2MIL)" at 12342.46,5845.9 h60
  text "MINIMUM ANNULAR RING" at 11318.23,5837.67 h60
  text "EXTERNAL" at 13050.46,5837.67 h60
  text "PER" at 11518.23,5727.55 h60
  text "IPC-D-275 CLASS 2 LEVEL C" at 11738.23,5727.54 h60
  text "MIL, HOLES" at 13226.46,5627.07 h60
  text "+/-" at 12834,5618.48 h60
  text "+/-" at 13688,5618.48 h60
  text "REGISTRATION TOLERANCES:" at 11318.23,5617.42 h60
  text "METAL" at 12518,5617.42 h60
  text "5" at 13094.2,5617.42 h60
  text "3" at 13927.2,5617.42 h60
  text "MIL" at 14043.46,5617.42 h60
  text "HOLE SIZE TOLERANCE (UNLESS OTHERWISE SPECIFIED):" at 11318.23,5519.1 h60
  text "+/-" at 13688,5516.23 h60
  text "3" at 13927.2,5515.17 h60
  text "MIL" at 14043.46,5515.17 h60
  text "MATERIAL:" at 11243.46,5377.52 h60
  text "FR-4 High Tg" at 12229.9,5249 h60
  text "X" at 12085.46,5241.01 h60
  text "FR-408" at 11664.46,5236.49 h60
  text "OTHER" at 13152.46,5236.49 h60
  text "62 MIL (1.6mm) +/-10%" at 11984.56,5093.46 h60
  text "X" at 11864.46,5091.01 h60
  text "THICKNESS:" at 11318.23,5085.24 h60
  text "OTHER" at 13269.46,5085.24 h60
  text "TOLERANCE:" at 11318.23,4946.92 h60
  text "X" at 12166.46,4946.92 h60
  text "ANSI IPC-6012 TYPE 3 CLASS 2" at 12344.48,4946.92 h60
  text "OTHER +/-" at 12344.46,4802.73 h60
  text "BOW & TWIST:" at 11318.23,4657.54 h60
  text "X" at 12166.46,4657.54 h60
  text "ANSI IPC-6012 TYPE 3 CLASS 2" at 12344.48,4657.54 h60
  text "OTHER +/-" at 12344.46,4510.85 h60
  text "DRILLING:" at 11243.46,4380.23 h60
  text "NC_DRILL FILES" at 13004.46,4275.04 h60
  text "REFERENCE:" at 11318.23,4271.1 h60
  text "X" at 11975.46,4271.01 h60
  text "AS SHOWN" at 12153.46,4271.1 h60
  text "X" at 12876.46,4271.1 h60
  text "OTHER" at 13302.46,4128.85 h60
  text "PTH COPPER THICKNESS:" at 11317.91,4125.32 h60
  text "X" at 12457.14,4125.32 h60
  text "20-30 um" at 12585.14,4125.32 h60
  text "BOARD FINISH:" at 11243.46,3977.73 h60
  text "SILKSCREEN:" at 11398.68,3867.6 h60
  text "X" at 12356.46,3867.6 h60
  text "TOP" at 12473.46,3867.6 h60
  text "X" at 12866.46,3867.6 h60
  text "BOTTOM" at 12984.46,3867.6 h60
  text "SILKSCREEN COLOR:" at 11398.68,3712.41 h60
  text "X" at 12355.46,3712.41 h60
  text "WHITE" at 12473.46,3712.41 h60
  text "OTHER" at 12984.46,3712.41 h60
  text "X" at 12486.46,3568.96 h60
  text "GREEN" at 12604.46,3568.96 h60
  text "OTHER" at 13222.46,3568.96 h60
  text "SOLDER RESIST COLOR:" at 11398.68,3562.1 h60
  text "X" at 12486.46,3414.71 h60
  text "MATTE" at 12604.46,3414.71 h60
  text "SEMI-GLOSS" at 13222,3414.07 h60
  text "IMMERSION GOLD (ENIG)" at 12304.46,3241.94 h60
  text "ENEPIG" at 13642,3234.72 h60
  text "SURFACE FINISH:" at 11243.46,3233.72 h60
  text "X" at 12126.46,3233.72 h60
  text "IMM. TIN/SILVER OR EQUIV" at 11573,3096.4 h60
  text "OTHER" at 13004.46,3092.47 h60
  text "ARRAY/PANEL:" at 11243.46,2937.09 h60
  text "CUT AND TRIM PER M1 BOARD OUTLINE" at 12304.46,2928.87 h60
  text "N.C. ROUTE" at 12304.46,2792.9 h60
  text "X" at 12992.46,2792.9 h60
  text "V. SCORE" at 13170.46,2792.9 h60
  text "CERTIFICATION:" at 11243.46,2663.77 h60
  text "MATERIALS AND WORKMANSHIP FOR ALL PCBS" at 11968.46,2663.77 h60
  text "TO MEET OR EXCEED THE REQUIREMENTS OF:" at 11968.46,2569.71 h60
  text "X" at 11605.97,2441.08 h60
  text "ANSI IPC-A-600F CLASS ->" at 11733.96,2441.08 h60
  text "X" at 13381.97,2441.08 h60
  text "2" at 13491.96,2441.08 h60
  text "1" at 13176.96,2439.58 h60
  text "3" at 13845.96,2439.58 h60
  text "X" at 12417.97,2293.39 h60
  text "RoHS" at 12545.96,2293.39 h60
  text "OTHER" at 13190.36,2293.39 h60
  text "PER ORDER" at 13587.42,2293.39 h60
  text "ALL BOARDS MUST MEET OR EXCEED UL94-V0 REQUIREMENTS." at 11271,2139.57 h60
  text "PCB MUST BEAR THE UL94V-0 UL REGISTERED MATERIAL ID NUMBER" at 11271,2023.5 h60
  text "ADDITIONAL REQUIREMENTS:" at 11243.46,1854.08 h60
  text "MICROSECTION:" at 11318.23,1746.95 h60
  text "YES" at 12223.96,1746.95 h60
  text "REQUIRED" at 13085.46,1602.62 h60
  text "BARE BOARD ELEC. TEST:" at 11318.23,1599.76 h60
  text "NONE" at 12623.96,1599.76 h60
  text "X" at 12967.46,1599.76 h60
  text "PER ORDER" at 13677.46,1599.76 h60
  text "XX MIL VIAS REQUIRE NON-CONDUCTIVE FILL AND PLANARIZE" at 11486.38,1394.82 h59
  text "XX MIL VIAS REQUIRE CONDUCTIVE FILL AND PLANARIZE" at 11494.38,1290.84 h60
  text "OUTER XX MIL VIAS REQUIRE 50 OHM SINGLE-ENDED IMPEDANCE" at 11493.39,1127.46 h58
  text "LAYER 2 & 3 (INNER LAYERS) XX MIL WIDE, XX MIL SPACE / TRACES REQUIRE 100 OHM DIFFERENTIAL IMPEDANCE" at 11485.39,891.74 h60
  text ".Layer_Name" at 487,-858.49 h60
M11 Gerber Information:
  lines w10: -382,-930.17 6218,-930.17 ; -382,-726.83 6220,-726.83 ; -382,-523.5 -382,-1133.5 3623,-1133.5 6220,-1133.5 6220,-523.5 -381.5,-523.5 -381.5,-1133.5 1194,-1133.5 ; 2083,-1133.5 2083,-523.5 ; 3350,-726.83 3350,-523.5 ; 4190,-726.83 4190,-523.5 ; 4812,-1140 4812,-937.17
  text "ALL ARTWORK VIEWED FROM TOP SIDE" at -318.5,-655.67 h60
  text "BOARD #:" at 2158,-655.67 h60
  text ".PRJ_Number" at 2703.5,-655.67 h60
  text "REV:" at 3548,-655.67 h60
  text ".PCB_Rev" at 3839.5,-655.67 h60
  text "SVN REV:" at 4386,-655.67 h60
  text ".VersionControl_RevNumber" at 4892,-655.67 h60
  text "LAYER NAME =" at -318.5,-858.49 h60
  text "TID #:" at 2158,-859 h60
  text ".TID" at 2703.5,-859 h60
  text "PLOT NAME =" at -318.5,-1064.34 h60
  text ".plot_File_Name" at 487,-1064.34 h60
  text "GENERATED    :" at 2160,-1064.34 h60
  text ".Print_Date" at 3029.5,-1064.34 h60
  text ".Print_Time" at 3758.5,-1064.34 h60
  text "TEXAS INSTRUMENTS" at 5023,-1064.34 h60
M12 Stackup:
  drawing of 191 lines, arcs and shapes, not listed
  text "Layer" at 9707.84,7830 h60
  text "Name" at 10117.76,7830 h60
  text "Material" at 11047.5,7830 h60
  text "Thickness" at 11907.27,7830 h60
  text "Constant" at 12557.1,7830 h60
  text "Board Layer Stack" at 13126.96,7830 h60
  text "1" at 9707.84,7710 h60
  text "Top Overlay" at 10117.76,7710 h60
  text "2" at 9707.84,7590 h60
  text "Top Solder" at 10117.76,7590 h60
  text "Solder Resist" at 11047.5,7590 h60
  text "0.40mil" at 11907.27,7590 h60
  text "3.5" at 12557.1,7590 h60
  text "3" at 9707.84,7470 h60
  text "Top Layer" at 10117.76,7470 h60
  text "Copper" at 11047.5,7470 h60
  text "1.40mil" at 11907.27,7470 h60
  text "4" at 9707.84,7350 h60
  text "Dielectric1" at 10117.76,7350 h60
  text "FR-4" at 11047.5,7350 h60
  text "58.40mil" at 11907.27,7350 h60
  text "4.8" at 12557.1,7350 h60
  text "5" at 9707.84,7230 h60
  text "Bottom Layer" at 10117.76,7230 h60
  text "Copper" at 11047.5,7230 h60
  text "1.40mil" at 11907.27,7230 h60
  text "6" at 9707.84,7110 h60
  text "Bottom Solder" at 10117.76,7110 h60
  text "Solder Resist" at 11047.5,7110 h60
  text "0.40mil" at 11907.27,7110 h60
  text "3.5" at 12557.1,7110 h60
  text "7" at 9707.84,6990 h60
  text "Bottom Overlay" at 10117.76,6990 h60
  text ".Layer_Name" at 487,-858.49 h60
M13 Component Bodies Top:
  text ".Layer_Name" at 487,-858.49 h60
M14 Component Bodies Bottom:
  text ".Layer_Name" at 487,-858.49 h60
M15 Courtyards Top:
  text ".Layer_Name" at 487,-858.49 h60
M16 Courtyards Bottom:
  text ".Layer_Name" at 487,-858.49 h60
Drill Drawing:
  lines w10: 5246.04,2866.37 5301.23,2866.37 5301.23,2921.56 5246.04,2921.56 5246.04,2866.37 ; 5246.04,3045.74 5301.23,3045.74 5273.63,2990.55 5246.04,3045.74 ; 5246.04,3128.52 5259.83,3128.52 5259.83,3114.72 5287.43,3114.72 5287.43,3128.52 5301.23,3128.52 5301.23,3156.12 5287.43,3156.12 5287.43,3169.91 5259.83,3169.91 5259.83,3156.12 5246.04,3156.12 5246.04,3128.52 ; 5246.04,3238.9 5273.63,3252.7 5301.23,3238.9 5287.43,3266.5 5301.23,3294.09 5273.63,3280.29 5246.04,3294.09 5259.83,3266.5 5246.04,3238.9
  lines w12: 5196,2829.12 8426.52,2829.12 ; 5196,3325.82 8426.52,3325.82 ; 5533.86,2704.94 5533.86,3450 ; 5865.86,2704.94 5865.86,3450 ; 6502.42,2704.94 6502.42,3450 ; 6761.53,2704.94 6761.53,3450 ; 7136.68,2704.94 7136.68,3450 ; 7860.06,2704.94 7860.06,3450 ; 5196,2704.94 8426.52,2704.94 8426.52,3450 5196,3450 5196,2704.94
  text "Symbol" at 5270.51,3363.08 h72
  text "Quantity" at 5571.11,3363.08 h72
  text "Finished Hole Size" at 5903.12,3363.08 h72
  text "Plated" at 6539.67,3363.08 h72
  text "Hole Type" at 6798.78,3363.08 h72
  text "Drill Layer Pair" at 7173.93,3363.08 h72
  text "Hole Tolerance" at 7897.32,3363.08 h72
  text "4" at 5571.11,3238.9 h60
  text "7.87mil (0.200mm)" at 5903.12,3238.9 h60
  text "PTH" at 6539.67,3238.9 h60
  text "Round" at 6798.78,3238.9 h60
  text "Top Layer - Bottom Layer" at 7173.93,3238.9 h60
  text "20" at 5571.11,3114.72 h60
  text "10.00mil (0.254mm)" at 5903.12,3114.72 h60
  text "PTH" at 6539.67,3114.72 h60
  text "Round" at 6798.78,3114.72 h60
  text "Top Layer - Bottom Layer" at 7173.93,3114.72 h60
  text "4" at 5571.11,2990.55 h60
  text "80.71mil (2.050mm)" at 5903.12,2990.55 h60
  text "PTH" at 6539.67,2990.55 h60
  text "Round" at 6798.78,2990.55 h60
  text "Top Layer - Bottom Layer" at 7173.93,2990.55 h60
  text "4" at 5571.11,2866.37 h60
  text "125.00mil (3.175mm)" at 5903.12,2866.37 h60
  text "PTH" at 6539.67,2866.37 h60
  text "Round" at 6798.78,2866.37 h60
  text "Top Layer - Bottom Layer" at 7173.93,2866.37 h60
  text "32 Total" at 5571.11,2742.2 h60
  text ".Layer_Name" at 487,-858.49 h60
M17 Embedded Cavity:
  text ".Layer_Name" at 487,-858.49 h60
M18 Embedded Assembly:
  text ".Layer_Name" at 487,-858.49 h60
M19 Embedded Keepout:
  text ".Layer_Name" at 487,-858.49 h60

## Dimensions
-90,-400 to 910,-400 on M2 Board Dimensions
0,0 to 1950,0 on M2 Board Dimensions
0,0 to 0,1400 on M2 Board Dimensions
